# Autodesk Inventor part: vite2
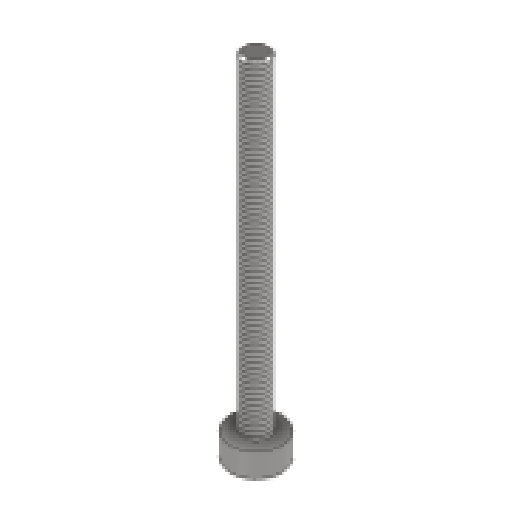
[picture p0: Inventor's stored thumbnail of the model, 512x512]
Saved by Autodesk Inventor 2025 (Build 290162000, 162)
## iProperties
Created: 2025-05
Part Number: vite2
Material: Acciaio inossidabile
Document SubType Name: Modeling
Designer: R5800u
Density: 8 g/cm^3
Appearance: Semilucidato
Author: R5800u
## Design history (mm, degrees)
sketch "Schizzo1"
  geometry: L1 (0, 0)-(4, 0); L2 (4, 0)-(4, 4); L3 (4, 4)-(2, 4); L4 (2, 4)-(2, 54); L5 (2, 54)-(0, 54); L6 (0, 54)-(0, 0)
  constraints: 12 end point, 4 perpendicular, 2 horizontal
  dimensions: "d0" = 4 distance of L1.start L1.end; "d1" = 4 distance of L1.end L2.end; "d3" = 50 distance of L3.end L4.end; "d4" = 2 distance between parallel lines of L4 L6
revolve "Rivoluzione1" sketch "Schizzo1" stored, may be unused: angle "d5" = 90 deg
sketch "Schizzo2"
  geometry: L1 (0, -1.5)-(-1.299, -0.75); L2 (-1.299, -0.75)-(-1.299, 0.75); L3 (-1.299, 0.75)-(0, 1.5); L4 (0, 1.5)-(1.299, 0.75); L5 (1.299, 0.75)-(1.299, -0.75); L6 (1.299, -0.75)-(0, -1.5); C1 r 4 at (0, 0) reference; 2 further points
  constraints: 12 end point, 1 coincident, 13 other
  dimensions: "d14" = 1.5 distance of L4.end L5.end
extrude "Estrusione1" cut sketch "Schizzo2" distance "d6" = 2; taper "d7" = 0 deg
chamfer "Smusso1" distance "d8" = 0.4; stored, may be unused: second distance "d9" = 2, angle "d10" = 45 deg
feature "Filettatura1" dims "d11" = 59.6, "d12" = 0
fillet "Raccordo1" dims "d13" = 0.5
node "Solido1"
